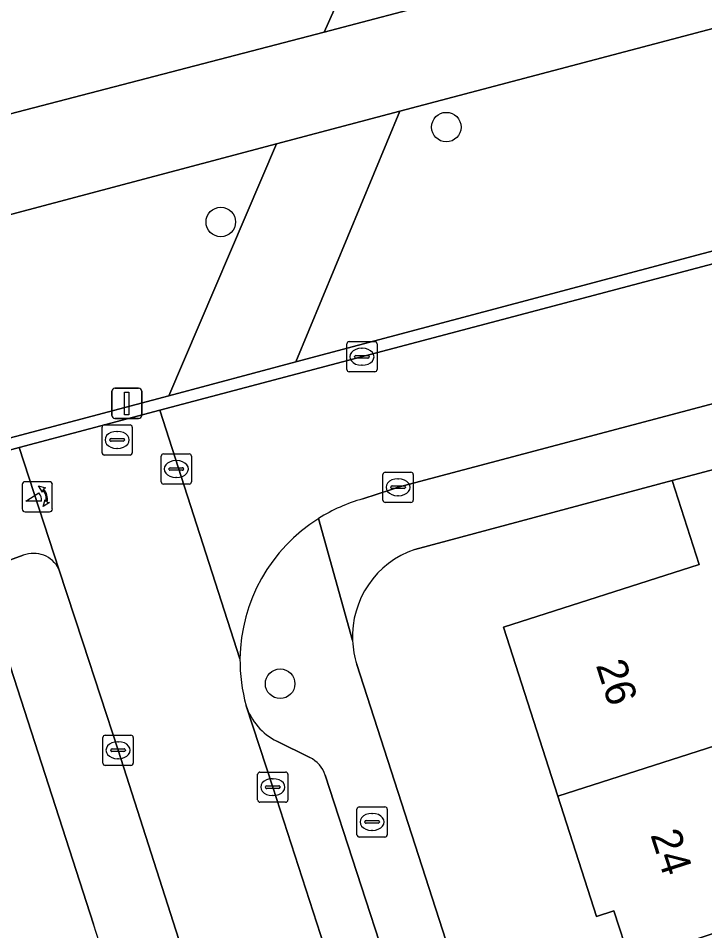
# Model space of a CAD drawing. Extents: x 162879 to 165540, y 384011 to 385181.
# Drawn here: x 163777.66 to 163800.4, y 384414.7 to 384444.93 of the extents above; entities that cross this region are included whole.
import ezdxf

# ---------------------------------------------------------------- set-up
doc = ezdxf.new("R2010")
doc.units = 0
for name, color, linetype in [('IMGEO_Boom', 7, 'Continuous'), ('IMGEO_Brandkraan', 7, 'Continuous'), ('IMGEO_Erf', 7, 'Continuous'), ('IMGEO_Fietspad_gesloten', 7, 'Continuous'), ('IMGEO_Groenvoorziening', 7, 'Continuous'), ('IMGEO_Haag', 7, 'Continuous'), ('IMGEO_Kolk', 7, 'Continuous'), ('IMGEO_Lichtmast', 7, 'Continuous'), ('IMGEO_Loofbos', 7, 'Continuous'), ('IMGEO_Pand', 7, 'Continuous'), ('IMGEO_Pand_nummerreeks', 7, 'Continuous'), ('IMGEO_Parkeervlak_open', 7, 'Continuous'), ('IMGEO_Poller', 7, 'Continuous'), ('IMGEO_Rijbaan_lokaal_open', 7, 'Continuous'), ('IMGEO_Rioolput', 7, 'Continuous'), ('IMGEO_Voetpad_halfverhard', 7, 'Continuous'), ('IMGEO_Voetpad_open', 7, 'Continuous')]:
    doc.layers.add(name, color=color, linetype=linetype)

msp = doc.modelspace()

# ---------------------------------------------------------------- linework, layer by layer
at = {"layer": 'IMGEO_Boom'}
for centre in [(163791.838, 384441.327), (163784.369, 384438.183), (163786.335, 384422.882)]:
    msp.add_circle(centre, 0.489, dxfattribs=at)
at = {"layer": 'IMGEO_Brandkraan'}
for p, q in [((163788.955, 384418.803), (163789.807, 384418.803)), ((163788.88, 384417.877), (163788.88, 384418.729)), ((163789.368, 384418.583), (163789.393, 384418.583)), ((163789.881, 384418.729), (163789.881, 384417.877)), ((163789.139, 384418.297), (163789.139, 384418.309)), ((163789.577, 384418.26), (163789.179, 384418.26)), ((163789.182, 384418.346), (163789.58, 384418.346)), ((163789.623, 384418.309), (163789.623, 384418.297)), ((163789.391, 384418.023), (163789.366, 384418.023)), ((163789.807, 384417.803), (163788.955, 384417.803))]:
    msp.add_line(p, q, dxfattribs=at)
for points in [[(163788.955, 384418.803), (163789.807, 384418.803)], [(163788.88, 384417.877), (163788.88, 384418.729)], [(163789.881, 384418.729), (163789.881, 384417.877)], [(163789.807, 384417.803), (163788.955, 384417.803)]]:
    msp.add_lwpolyline(points, dxfattribs=at)
for centre, radius, start, end in [((163788.957, 384418.727), 0.0765, 91.552, 178.448), ((163788.957, 384418.727), 0.0765, 91.552, 178.448), ((163789.805, 384418.727), 0.0765, 1.552, 88.448), ((163789.805, 384418.727), 0.0765, 1.552, 88.448), ((163789.179, 384418.306), 0.0403, 85.8775, 175.7526), ((163789.176, 384418.296), 0.0366, 178.938, 274.7102), ((163789.58, 384418.303), 0.043, 264.8664, 352.4533), ((163789.584, 384418.308), 0.0386, 1.7309, 96.639), ((163788.957, 384417.879), 0.0765, 181.552, 268.448), ((163788.957, 384417.879), 0.0765, 181.552, 268.448), ((163789.805, 384417.879), 0.0765, 271.552, 358.448), ((163789.805, 384417.879), 0.0765, 271.552, 358.448)]:
    msp.add_arc(centre, radius, start, end, dxfattribs=at)
for centre, major_axis, ratio, start_param, end_param in [((163789.367, 384418.303), (-0.387, 0.002), 0.722429, 4.712389, 7.853982), ((163789.392, 384418.303), (-0.39, 0.002), 0.717154, 1.570796, 4.712389)]:
    msp.add_ellipse(centre, major_axis=major_axis, ratio=ratio, start_param=start_param, end_param=end_param, dxfattribs=at)
at = {"layer": 'IMGEO_Erf'}
for points in [[(163804.622, 384412.635), (163803.766, 384415.619), (163797.929, 384413.701), (163797.388, 384415.352), (163796.816, 384415.168), (163795.534, 384419.157), (163793.736, 384424.755), (163800.21, 384426.836), (163799.316, 384429.621), (163790.794, 384427.333)], [(163788.875, 384423.518), (163792.049, 384413.663)]]:
    msp.add_lwpolyline(points, dxfattribs=at)
for centre, radius, start, end in [((163791.778, 384424.448), 3.048, 108.8302, 182.5996), ((163791.8, 384424.451), 3.07, 182.6349, 197.6946)]:
    msp.add_arc(centre, radius, start, end, dxfattribs=at)
at = {"layer": 'IMGEO_Fietspad_gesloten'}
for points in [[(163779.007, 384426.681), (163777.69, 384430.711), (163775.3, 384430.061), (163774.966, 384429.974), (163771.751, 384429.132), (163776.651, 384413.901)], [(163780.151, 384414.912), (163776.364, 384426.615), (163777.829, 384427.14)]]:
    msp.add_lwpolyline(points, dxfattribs=at)
for centre, radius, start, end in [((163778.167, 384426.266), 0.937, 26.3068, 111.1171), ((163578.641, 384347.699), 212.423, 7.31878, 18.44587)]:
    msp.add_arc(centre, radius, start, end, dxfattribs=at)
at = {"layer": 'IMGEO_Groenvoorziening'}
for points in [[(163791.82, 384445.529), (163797.518, 384459.112), (163793.758, 384457.809), (163787.79, 384444.476)], [(163816.786, 384441.509), (163810.694, 384447.259), (163790.298, 384441.853), (163786.859, 384433.545)], [(163790.298, 384441.853), (163786.21, 384440.769), (163782.654, 384432.426), (163786.859, 384433.545)]]:
    msp.add_lwpolyline(points, close=True, dxfattribs=at)
for points in [[(163846.564, 384455.941), (163848.959, 384450.828), (163848.448, 384449.933), (163839.54, 384447.563), (163836.128, 384446.655), (163824.084, 384443.45), (163816.786, 384441.509), (163786.859, 384433.545), (163782.654, 384432.426), (163775.562, 384430.545), (163773.371, 384437.23)], [(163773.081, 384436.833), (163775.3, 384430.061), (163777.69, 384430.711), (163782.356, 384431.947), (163812.597, 384439.959), (163829.593, 384444.462), (163830.022, 384444.577), (163841.66, 384447.709), (163843.285, 384448.142), (163848.713, 384449.59)], [(163773.371, 384437.23), (163775.562, 384430.545), (163782.654, 384432.426), (163786.21, 384440.769)], [(163786.21, 384440.769), (163773.948, 384437.519)], [(163777.829, 384427.14), (163776.364, 384426.615), (163780.151, 384414.912)], [(163788.792, 384392.978), (163787.888, 384396.88), (163786.914, 384400.782), (163786.348, 384402.953), (163785.764, 384405.127), (163783.795, 384411.861), (163780.97, 384420.679), (163779.798, 384424.262), (163779.007, 384426.681)]]:
    msp.add_lwpolyline(points, dxfattribs=at)
for centre, radius, start, end in [((163778.167, 384426.266), 0.937, 26.3068, 111.1171), ((163578.641, 384347.699), 212.423, 7.31878, 18.44587)]:
    msp.add_arc(centre, radius, start, end, dxfattribs=at)
at = {"layer": 'IMGEO_Haag'}
for points in [[(163846.564, 384455.941), (163848.959, 384450.828), (163848.448, 384449.933), (163839.54, 384447.563), (163836.128, 384446.655), (163824.084, 384443.45), (163816.786, 384441.509), (163786.859, 384433.545), (163782.654, 384432.426), (163775.562, 384430.545), (163773.371, 384437.23)], [(163773.081, 384436.833), (163775.3, 384430.061), (163777.69, 384430.711), (163782.356, 384431.947), (163812.597, 384439.959), (163829.593, 384444.462), (163830.022, 384444.577), (163841.66, 384447.709), (163843.285, 384448.142), (163848.713, 384449.59)]]:
    msp.add_lwpolyline(points, dxfattribs=at)
at = {"layer": 'IMGEO_Kolk'}
for p, q in [((163788.543, 384433.292), (163788.543, 384434.144)), ((163788.618, 384434.218), (163789.47, 384434.218)), ((163789.031, 384433.998), (163789.056, 384433.998)), ((163789.544, 384434.144), (163789.544, 384433.292)), ((163788.802, 384433.712), (163788.802, 384433.724)), ((163789.24, 384433.675), (163788.842, 384433.675)), ((163788.845, 384433.761), (163789.243, 384433.761)), ((163789.286, 384433.724), (163789.286, 384433.712)), ((163789.054, 384433.438), (163789.029, 384433.438)), ((163789.47, 384433.218), (163788.618, 384433.218)), ((163789.741, 384428.966), (163789.741, 384429.818)), ((163789.816, 384429.892), (163790.668, 384429.892)), ((163790.742, 384429.818), (163790.742, 384428.966)), ((163790, 384429.386), (163790, 384429.398)), ((163790.043, 384429.435), (163790.441, 384429.435)), ((163790.229, 384429.672), (163790.254, 384429.672)), ((163790.484, 384429.398), (163790.484, 384429.386)), ((163790.438, 384429.349), (163790.04, 384429.349)), ((163790.252, 384429.112), (163790.227, 384429.112)), ((163790.668, 384428.892), (163789.816, 384428.892)), ((163780.468, 384420.252), (163780.468, 384421.104)), ((163780.543, 384421.178), (163781.395, 384421.178)), ((163780.956, 384420.958), (163780.981, 384420.958)), ((163781.469, 384421.104), (163781.469, 384420.252)), ((163780.727, 384420.672), (163780.727, 384420.684)), ((163781.165, 384420.635), (163780.767, 384420.635)), ((163780.77, 384420.721), (163781.168, 384420.721)), ((163781.211, 384420.684), (163781.211, 384420.672)), ((163780.979, 384420.398), (163780.954, 384420.398)), ((163781.395, 384420.178), (163780.543, 384420.178)), ((163785.591, 384419.03), (163785.591, 384419.882)), ((163785.666, 384419.956), (163786.518, 384419.956)), ((163786.079, 384419.736), (163786.104, 384419.736)), ((163786.592, 384419.882), (163786.592, 384419.03)), ((163785.85, 384419.45), (163785.85, 384419.462)), ((163786.288, 384419.413), (163785.89, 384419.413)), ((163785.893, 384419.499), (163786.291, 384419.499)), ((163786.334, 384419.462), (163786.334, 384419.45)), ((163786.102, 384419.176), (163786.077, 384419.176)), ((163786.518, 384418.956), (163785.666, 384418.956))]:
    msp.add_line(p, q, dxfattribs=at)
for points in [[(163788.543, 384433.292), (163788.543, 384434.144)], [(163788.618, 384434.218), (163789.47, 384434.218)], [(163789.544, 384434.144), (163789.544, 384433.292)], [(163789.47, 384433.218), (163788.618, 384433.218)], [(163789.741, 384428.966), (163789.741, 384429.818)], [(163789.816, 384429.892), (163790.668, 384429.892)], [(163790.742, 384429.818), (163790.742, 384428.966)], [(163790.668, 384428.892), (163789.816, 384428.892)], [(163780.468, 384420.252), (163780.468, 384421.104)], [(163780.543, 384421.178), (163781.395, 384421.178)], [(163781.469, 384421.104), (163781.469, 384420.252)], [(163781.395, 384420.178), (163780.543, 384420.178)], [(163785.591, 384419.03), (163785.591, 384419.882)], [(163785.666, 384419.956), (163786.518, 384419.956)], [(163786.592, 384419.882), (163786.592, 384419.03)], [(163786.518, 384418.956), (163785.666, 384418.956)]]:
    msp.add_lwpolyline(points, dxfattribs=at)
for centre, radius, start, end in [((163788.62, 384434.142), 0.0765, 91.552, 178.448), ((163788.62, 384434.142), 0.0765, 91.552, 178.448), ((163789.468, 384434.142), 0.0765, 1.552, 88.448), ((163789.468, 384434.142), 0.0765, 1.552, 88.448), ((163788.842, 384433.721), 0.0403, 85.8775, 175.7526), ((163788.839, 384433.711), 0.0366, 178.938, 274.7102), ((163789.243, 384433.718), 0.043, 264.8664, 352.4533), ((163789.247, 384433.723), 0.0386, 1.7309, 96.639), ((163788.62, 384433.294), 0.0765, 181.552, 268.448), ((163788.62, 384433.294), 0.0765, 181.552, 268.448), ((163789.468, 384433.294), 0.0765, 271.552, 358.448), ((163789.468, 384433.294), 0.0765, 271.552, 358.448), ((163789.818, 384429.816), 0.0765, 91.552, 178.448), ((163789.818, 384429.816), 0.0765, 91.552, 178.448), ((163790.666, 384429.816), 0.0765, 1.552, 88.448), ((163790.666, 384429.816), 0.0765, 1.552, 88.448), ((163790.04, 384429.395), 0.0403, 85.8775, 175.7526), ((163790.037, 384429.385), 0.0366, 178.938, 274.7102), ((163790.441, 384429.392), 0.043, 264.8664, 352.4533), ((163790.445, 384429.397), 0.0386, 1.7309, 96.639), ((163789.818, 384428.968), 0.0765, 181.552, 268.448), ((163789.818, 384428.968), 0.0765, 181.552, 268.448), ((163790.666, 384428.968), 0.0765, 271.552, 358.448), ((163790.666, 384428.968), 0.0765, 271.552, 358.448), ((163780.545, 384421.102), 0.0765, 91.552, 178.448), ((163780.545, 384421.102), 0.0765, 91.552, 178.448), ((163781.393, 384421.102), 0.0765, 1.552, 88.448), ((163781.393, 384421.102), 0.0765, 1.552, 88.448), ((163780.767, 384420.681), 0.0403, 85.8775, 175.7526), ((163780.764, 384420.671), 0.0366, 178.938, 274.7102), ((163781.168, 384420.678), 0.043, 264.8664, 352.4533), ((163781.172, 384420.683), 0.0386, 1.7309, 96.639), ((163780.545, 384420.254), 0.0765, 181.552, 268.448), ((163780.545, 384420.254), 0.0765, 181.552, 268.448), ((163781.393, 384420.254), 0.0765, 271.552, 358.448), ((163781.393, 384420.254), 0.0765, 271.552, 358.448), ((163785.668, 384419.88), 0.0765, 91.552, 178.448), ((163785.668, 384419.88), 0.0765, 91.552, 178.448), ((163786.516, 384419.88), 0.0765, 1.552, 88.448), ((163786.516, 384419.88), 0.0765, 1.552, 88.448), ((163785.89, 384419.459), 0.0403, 85.8775, 175.7526), ((163785.887, 384419.449), 0.0366, 178.938, 274.7102), ((163786.291, 384419.456), 0.043, 264.8664, 352.4533), ((163786.295, 384419.461), 0.0386, 1.7309, 96.639), ((163785.668, 384419.032), 0.0765, 181.552, 268.448), ((163785.668, 384419.032), 0.0765, 181.552, 268.448), ((163786.516, 384419.032), 0.0765, 271.552, 358.448), ((163786.516, 384419.032), 0.0765, 271.552, 358.448)]:
    msp.add_arc(centre, radius, start, end, dxfattribs=at)
for centre, major_axis, ratio, start_param, end_param in [((163789.03, 384433.718), (-0.387, 0.002), 0.722429, 4.712389, 7.853982), ((163789.055, 384433.718), (-0.39, 0.002), 0.717154, 1.570796, 4.712389), ((163790.228, 384429.392), (-0.387, 0.002), 0.722429, 4.712389, 7.853982), ((163790.253, 384429.392), (-0.39, 0.002), 0.717154, 1.570796, 4.712389), ((163780.955, 384420.678), (-0.387, 0.002), 0.722429, 4.712389, 7.853982), ((163780.98, 384420.678), (-0.39, 0.002), 0.717154, 1.570796, 4.712389), ((163786.078, 384419.456), (-0.387, 0.002), 0.722429, 4.712389, 7.853982), ((163786.103, 384419.456), (-0.39, 0.002), 0.717154, 1.570796, 4.712389)]:
    msp.add_ellipse(centre, major_axis=major_axis, ratio=ratio, start_param=start_param, end_param=end_param, dxfattribs=at)
at = {"layer": 'IMGEO_Lichtmast'}
for p, q in [((163780.76, 384431.773), (163780.76, 384432.573)), ((163780.76, 384432.573), (163780.76, 384431.773)), ((163780.86, 384432.673), (163781.65, 384432.673)), ((163781.65, 384432.673), (163780.86, 384432.673)), ((163781.75, 384432.573), (163781.75, 384431.773)), ((163781.75, 384431.773), (163781.75, 384432.573)), ((163781.65, 384431.673), (163780.86, 384431.673)), ((163780.86, 384431.673), (163781.65, 384431.673))]:
    msp.add_line(p, q, dxfattribs=at)
msp.add_lwpolyline([(163781.18, 384432.548), (163781.33, 384432.548), (163781.33, 384431.798), (163781.18, 384431.798), (163781.18, 384432.548)], dxfattribs=at)
for centre, start, end in [((163780.86, 384432.573), 90, 180), ((163780.86, 384432.573), 90, 180), ((163781.65, 384432.573), 0, 90), ((163781.65, 384432.573), 360, 90), ((163780.86, 384431.773), 180, 270), ((163780.86, 384431.773), 180, 270), ((163781.65, 384431.773), 270, 0), ((163781.65, 384431.773), 270, 0)]:
    msp.add_arc(centre, 0.1, start, end, dxfattribs=at)
at = {"layer": 'IMGEO_Loofbos'}
msp.add_lwpolyline([(163787.79, 384444.476), (163793.758, 384457.809), (163758.484, 384448.385), (163767.725, 384439.247)], close=True, dxfattribs=at)
at = {"layer": 'IMGEO_Pand'}
for points in [[(163806.243, 384422.592), (163804.524, 384427.941), (163806.752, 384428.658), (163805.887, 384431.366), (163799.316, 384429.621), (163800.21, 384426.836), (163793.736, 384424.755), (163795.534, 384419.157)], [(163806.243, 384422.592), (163795.534, 384419.157), (163796.816, 384415.168), (163797.388, 384415.352), (163797.929, 384413.701), (163803.766, 384415.619), (163804.622, 384412.635), (163811.223, 384414.483), (163810.195, 384418.068), (163807.931, 384417.34)]]:
    msp.add_lwpolyline(points, close=True, dxfattribs=at)
at = {"layer": 'IMGEO_Parkeervlak_open'}
for points in [[(163785.209, 384422.153), (163786.091, 384419.455), (163788.156, 384413.074)], [(163787.318, 384420.436), (163786.226, 384420.98)], [(163794.65, 384395.502), (163792.131, 384405.702), (163790.509, 384411.482), (163789.922, 384413.4), (163787.826, 384419.852)]]:
    msp.add_lwpolyline(points, dxfattribs=at)
for centre, radius, start, end in [((163787.132, 384422.793), 2.027, 198.4101, 243.441), ((163786.916, 384419.573), 0.952, 17.031, 65.0066)]:
    msp.add_arc(centre, radius, start, end, dxfattribs=at)
at = {"layer": 'IMGEO_Poller'}
for p, q in [((163777.795, 384429.48), (163777.795, 384428.673)), ((163777.795, 384429.48), (163777.795, 384428.673)), ((163778.697, 384429.575), (163777.889, 384429.575)), ((163778.697, 384429.575), (163777.889, 384429.575)), ((163778.791, 384428.673), (163778.791, 384429.48)), ((163778.791, 384428.673), (163778.791, 384429.48)), ((163777.889, 384428.578), (163778.697, 384428.578)), ((163777.889, 384428.578), (163778.697, 384428.578))]:
    msp.add_line(p, q, dxfattribs=at)
for points in [[(163778.474, 384429.304), (163778.462, 384429.231), (163778.337, 384429.436)], [(163778.337, 384429.436), (163778.568, 384429.37), (163778.497, 384429.338)], [(163778.43, 384428.931), (163777.917, 384428.931), (163778.347, 384429.206)], [(163778.49, 384428.759), (163778.556, 384428.99), (163778.586, 384428.922)], [(163778.622, 384428.895), (163778.694, 384428.884), (163778.49, 384428.759)]]:
    msp.add_lwpolyline(points, dxfattribs=at)
for centre, radius, start, end in [((163777.889, 384429.48), 0.0946, 90, 180), ((163777.889, 384429.48), 0.0946, 90, 180), ((163778.697, 384429.48), 0.0946, 0, 90), ((163778.697, 384429.48), 0.0946, 0, 90), ((163778.102, 384428.981), 0.332, 351.3247, 42.4854), ((163778.116, 384428.991), 0.476, 351.7527, 41.1691), ((163778.116, 384428.991), 0.516, 349.3569, 42.2912), ((163777.889, 384428.673), 0.0946, 180, 270), ((163777.889, 384428.673), 0.0946, 180, 270), ((163778.697, 384428.673), 0.0946, 270, 0), ((163778.697, 384428.673), 0.0946, 270, 0)]:
    msp.add_arc(centre, radius, start, end, dxfattribs=at)
at = {"layer": 'IMGEO_Rijbaan_lokaal_open'}
for points in [[(163816.688, 384436.424), (163827.864, 384439.385), (163828.078, 384439.436), (163833.898, 384440.995), (163844.487, 384443.826), (163843.285, 384448.142), (163841.66, 384447.709), (163830.022, 384444.577), (163829.593, 384444.462), (163812.597, 384439.959), (163782.356, 384431.947), (163785.005, 384423.713)], [(163789.071, 384429.007), (163790.022, 384429.323), (163790.242, 384429.393), (163810.672, 384434.817), (163810.892, 384434.883), (163816.688, 384436.424)], [(163785.005, 384423.713), (163782.356, 384431.947), (163777.69, 384430.711), (163779.007, 384426.681), (163779.798, 384424.262), (163780.97, 384420.679), (163783.795, 384411.861), (163785.764, 384405.127), (163786.348, 384402.953), (163786.914, 384400.782), (163787.888, 384396.88), (163788.792, 384392.978)], [(163786.091, 384419.455), (163785.209, 384422.153)], [(163788.156, 384413.074), (163786.091, 384419.455)]]:
    msp.add_lwpolyline(points, dxfattribs=at)
for centre, radius, start, end in [((163790.561, 384423.667), 5.544, 105.5887, 122.1468), ((163790.566, 384423.65), 5.561, 122.0962, 179.3476), ((163790.503, 384423.639), 5.498, 179.2245, 195.676)]:
    msp.add_arc(centre, radius, start, end, dxfattribs=at)
at = {"layer": 'IMGEO_Rioolput'}
for p, q in [((163780.437, 384430.535), (163780.437, 384431.387)), ((163780.512, 384431.461), (163781.364, 384431.461)), ((163780.925, 384431.241), (163780.95, 384431.241)), ((163781.438, 384431.387), (163781.438, 384430.535)), ((163780.696, 384430.955), (163780.696, 384430.967)), ((163781.134, 384430.918), (163780.736, 384430.918)), ((163780.739, 384431.004), (163781.137, 384431.004)), ((163781.18, 384430.967), (163781.18, 384430.955)), ((163780.948, 384430.681), (163780.923, 384430.681)), ((163781.364, 384430.461), (163780.512, 384430.461)), ((163782.395, 384429.571), (163782.395, 384430.423)), ((163782.47, 384430.497), (163783.322, 384430.497)), ((163783.396, 384430.423), (163783.396, 384429.571)), ((163782.654, 384429.991), (163782.654, 384430.003)), ((163782.697, 384430.04), (163783.095, 384430.04)), ((163782.883, 384430.277), (163782.908, 384430.277)), ((163783.138, 384430.003), (163783.138, 384429.991)), ((163783.092, 384429.954), (163782.694, 384429.954)), ((163782.906, 384429.717), (163782.881, 384429.717)), ((163783.322, 384429.497), (163782.47, 384429.497))]:
    msp.add_line(p, q, dxfattribs=at)
for points in [[(163780.437, 384430.535), (163780.437, 384431.387)], [(163780.512, 384431.461), (163781.364, 384431.461)], [(163781.438, 384431.387), (163781.438, 384430.535)], [(163781.364, 384430.461), (163780.512, 384430.461)], [(163782.395, 384429.571), (163782.395, 384430.423)], [(163782.47, 384430.497), (163783.322, 384430.497)], [(163783.396, 384430.423), (163783.396, 384429.571)], [(163783.322, 384429.497), (163782.47, 384429.497)]]:
    msp.add_lwpolyline(points, dxfattribs=at)
for centre, radius, start, end in [((163780.514, 384431.385), 0.0765, 91.552, 178.448), ((163780.514, 384431.385), 0.0765, 91.552, 178.448), ((163781.362, 384431.385), 0.0765, 1.552, 88.448), ((163781.362, 384431.385), 0.0765, 1.552, 88.448), ((163780.736, 384430.964), 0.0403, 85.8775, 175.7526), ((163780.733, 384430.954), 0.0366, 178.938, 274.7102), ((163781.137, 384430.961), 0.043, 264.8664, 352.4533), ((163781.141, 384430.966), 0.0386, 1.7309, 96.639), ((163780.514, 384430.537), 0.0765, 181.552, 268.448), ((163780.514, 384430.537), 0.0765, 181.552, 268.448), ((163781.362, 384430.537), 0.0765, 271.552, 358.448), ((163781.362, 384430.537), 0.0765, 271.552, 358.448), ((163782.472, 384430.421), 0.0765, 91.552, 178.448), ((163782.472, 384430.421), 0.0765, 91.552, 178.448), ((163783.32, 384430.421), 0.0765, 1.552, 88.448), ((163783.32, 384430.421), 0.0765, 1.552, 88.448), ((163782.694, 384430), 0.0403, 85.8775, 175.7526), ((163782.691, 384429.99), 0.0366, 178.938, 274.7102), ((163783.095, 384429.997), 0.043, 264.8664, 352.4533), ((163783.099, 384430.002), 0.0386, 1.7309, 96.639), ((163782.472, 384429.573), 0.0765, 181.552, 268.448), ((163782.472, 384429.573), 0.0765, 181.552, 268.448), ((163783.32, 384429.573), 0.0765, 271.552, 358.448), ((163783.32, 384429.573), 0.0765, 271.552, 358.448)]:
    msp.add_arc(centre, radius, start, end, dxfattribs=at)
for centre, major_axis, ratio, start_param, end_param in [((163780.924, 384430.961), (-0.387, 0.002), 0.722429, 4.712389, 7.853982), ((163780.949, 384430.961), (-0.39, 0.002), 0.717154, 1.570796, 4.712389), ((163782.882, 384429.997), (-0.387, 0.002), 0.722429, 4.712389, 7.853982), ((163782.907, 384429.997), (-0.39, 0.002), 0.717154, 1.570796, 4.712389)]:
    msp.add_ellipse(centre, major_axis=major_axis, ratio=ratio, start_param=start_param, end_param=end_param, dxfattribs=at)
at = {"layer": 'IMGEO_Voetpad_halfverhard'}
for points in [[(163982.76, 384495.175), (163962.807, 384490.891), (163952.063, 384488.31), (163948.609, 384487.296), (163933.617, 384483.398), (163930.97, 384483.09), (163915.933, 384478.646), (163912.088, 384477.649), (163889.336, 384471.543), (163887.8, 384473.119), (163884.045, 384472.111), (163883.368, 384469.921), (163880.102, 384469.025), (163876.666, 384468.039), (163853.304, 384461.931), (163849.326, 384460.82), (163827.159, 384455.136), (163822.424, 384453.876), (163811.858, 384450.959), (163807.873, 384449.922), (163791.82, 384445.529), (163787.79, 384444.476), (163767.725, 384439.247), (163768.36, 384438.631)], [(163773.948, 384437.519), (163786.21, 384440.769), (163790.298, 384441.853), (163810.694, 384447.259), (163814.756, 384448.336), (163821.789, 384450.2), (163822.181, 384450.302), (163826.162, 384451.348), (163831.897, 384452.856), (163835.315, 384453.754), (163844.879, 384455.947), (163846.081, 384455.943), (163849.575, 384457.122), (163849.689, 384457.154), (163850.77, 384457.592), (163850.988, 384457.126), (163851.355, 384457.285), (163854.334, 384458.567), (163859.733, 384460.009), (163885.67, 384466.934)]]:
    msp.add_lwpolyline(points, dxfattribs=at)
at = {"layer": 'IMGEO_Voetpad_open'}
for points in [[(163844.487, 384443.826), (163833.898, 384440.995), (163834.015, 384440.558), (163828.203, 384439.02), (163828.078, 384439.436), (163827.864, 384439.385), (163816.688, 384436.424), (163816.813, 384435.986), (163811.005, 384434.458), (163810.892, 384434.883), (163810.672, 384434.817), (163790.242, 384429.393), (163790.022, 384429.323), (163789.071, 384429.007)], [(163790.794, 384427.333), (163799.316, 384429.621), (163805.887, 384431.366)], [(163788.733, 384424.31), (163787.611, 384428.361)], [(163787.611, 384428.361), (163788.733, 384424.31)], [(163792.049, 384413.663), (163788.875, 384423.518)], [(163786.226, 384420.98), (163787.318, 384420.436)], [(163787.826, 384419.852), (163789.922, 384413.4), (163790.509, 384411.482), (163790.939, 384411.614), (163792.567, 384405.819), (163792.131, 384405.702), (163794.65, 384395.502), (163795.101, 384395.605), (163796.348, 384389.718), (163795.908, 384389.617), (163796.842, 384384.196)]]:
    msp.add_lwpolyline(points, dxfattribs=at)
for centre, radius, start, end in [((163790.561, 384423.667), 5.544, 105.5887, 122.1468), ((163790.566, 384423.65), 5.561, 122.0962, 179.3476), ((163791.778, 384424.448), 3.048, 108.8302, 182.5996), ((163791.8, 384424.451), 3.07, 182.6349, 197.6946), ((163790.503, 384423.639), 5.498, 179.2245, 195.676), ((163787.132, 384422.793), 2.027, 198.4101, 243.441), ((163786.916, 384419.573), 0.952, 17.031, 65.0066)]:
    msp.add_arc(centre, radius, start, end, dxfattribs=at)

# ---------------------------------------------------------------- texts
at = {"layer": 'IMGEO_Pand_nummerreeks'}
for s, p in [('26', (163796.785, 384423.501)), ('24', (163798.591, 384417.878))]:
    msp.add_text(s, height=1, rotation=287.8106, dxfattribs=at).set_placement(p)

doc.saveas('drawing.dxf')
